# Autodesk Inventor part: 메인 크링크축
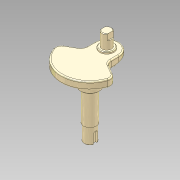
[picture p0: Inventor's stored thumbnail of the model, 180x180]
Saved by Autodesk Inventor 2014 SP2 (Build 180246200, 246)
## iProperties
Manager: KYOUNG IL JANG
Company: 한국ATC센터
Created: 2012-10
Part Number: 메인 크링크축
Document SubType Name: Modeling
Density: 1 g/cm^3
Checked By: KYOUNG IL JANG
Vendor: CBT Solutions
Designer: KYOUNG IL JANG
Material: 일반
Appearance: _시험_금속-티타늄(광택)
크링크폭: 19.000 mm
크랭크길이: 18.000 mm
크랭키위치: 65.000 mm
무게추: 90.000 mm
크랭크각도높이: 21.000 mm
크링크각도: -15.00 deg
Author: KYOUNG IL JANG
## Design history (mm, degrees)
sketch "스케치1"
  geometry: L1 (-19, 109.368)-(-19, 91.368); L2 (-19, 91.368)-(-44.545, 76.619); L3 (19, 109.368)-(19, 91.368); L4 (19, 91.368)-(44.545, 76.619); C1 r 32.5 at (0, 83) reference; C2 r 10 at (0, 83); C3 r 17.5 at (0, 83); A1 r 45 centre (0, 83) between (-44.545, 76.619) and (44.545, 76.619); A2 r 32.5 centre (0, 83) between (-19, 109.368) and (19, 109.368); A3 r 19 centre (0, 109.368) between (19, 109.368) and (-19, 109.368); 1 further point
  constraints: 8 end point, 6 point on circle, 5 centre point, 4 coincident, 2 equal length, 2 vertical alignment, 1 horizontal alignment, 1 parallel, 1 tangent, 1 vertical, 3 other
  dimensions: "d0" = 20 diameter of C2; "d1" = 35 diameter of C3; "d4" = 120 deg angle of L3 L4
  node "참조1"
extrude "돌출1" new body sketch "스케치1" distance "d7" = 12; taper "d8" = 0 deg
extrude "돌출2" join sketch "스케치1" distance "d9" = 5; taper "d10" = 0 deg
extrude "돌출3" join sketch "스케치1" distance "d11" = 100; taper "d12" = 0 deg
sketch "스케치2"
  geometry: C1 r 7.5 at (0, 109.368); C2 r 11 at (0, 109.368); A1 r 19 centre (0, 109.368) between (19, 109.368) and (-19, 109.368) reference; 1 further point
  constraints: 2 centre point, 2 coincident
  dimensions: "d13" = 15 diameter of C1; "d14" = 22 diameter of C2
extrude "돌출4" join sketch "스케치2" distance "d15" = 3; taper "d16" = 0 deg
extrude "돌출5" join sketch "스케치2" distance "d17" = 25; taper "d18" = 0 deg
node "작업 평면1"
sketch "스케치3"
  geometry: L1 (-5.75, 4.815)-(-5.75, -4.815); L2 (5.75, 4.815)-(5.75, -4.815); A1 r 7.5 centre (0, 0) between (-5.75, 4.815) and (-5.75, -4.815) reference; 1 further point
  constraints: 4 end point, 4 point on circle, 2 parallel, 1 vertical
  dimensions: "d20" = 11.5 distance between parallel lines of L2 L1
extrude "돌출6" cut sketch "스케치3" stored distance "d21" = 10; taper "d22" = 0 deg
sketch "스케치4"
  geometry: L1 (-19, 91.368)-(-19, 109.368) reference; L2 (19, 109.368)-(19, 91.368) reference; C1 r 17.5 at (0, 83) reference; 3 further points
  constraints: 2 point on line, 1 horizontal alignment, 1 other
node "작업 평면2"
  node "작업축1"
sketch "스케치5"
  geometry: L1 (0, 0)-(38, 0); L2 (38, 0)-(38, 50); L3 (38, 50)-(0, 50); L4 (0, 50)-(0, 0); L5 (38, 5.185)-(38, -12.202) reference; 2 further points
  constraints: 8 end point, 1 coincident, 1 collinear, 1 horizontal, 1 perpendicular
  dimensions: "d27" = 50 distance between parallel lines of L3 L1
extrude "돌출7" cut sketch "스케치5" stored distance "d28" = 10; taper "d29" = 0 deg
fillet "모깎기1" dims "d23" = 10, "d24" = 2
sketch "스케치6"
  geometry: C1 r 17.5 at (0, 0) reference; C2 r 15 at (0, 0); 1 further point
  constraints: 1 centre point, 1 coincident
  dimensions: "d30" = 30 diameter of C2
extrude "돌출8" join sketch "스케치6" distance "d31" = 21; taper "d32" = 0 deg
sketch "스케치7"
  geometry: C1 r 10 at (0, 0) reference; C2 r 9 at (0, 0); 1 further point
  constraints: 1 centre point, 1 coincident
  dimensions: "d33" = 1 radial gap between concentric circles of C1 C2
extrude "돌출9" cut sketch "스케치7" distance "d34" = 25; taper "d35" = 0 deg
node "작업 평면3"
sketch "스케치8"
  geometry: L1 (-9, 0)-(9, 0) reference; L2 (-3, 0)-(-3, 15); L3 (3, 15)-(3, 0); A1 r 3 centre (0, 15) between (3, 15) and (-3, 15); 2 further points
  constraints: 4 end point, 2 perpendicular, 2 point on circle, 2 point on line, 2 tangent, 1 centre point, 1 midpoint, 1 vertical alignment
  dimensions: "d36" = 6 distance between parallel lines of L3 L2; "d37" = 18 dimension on A1 L1
extrude "돌출10" cut sketch "스케치8" distance "d38" = 3.5; taper "d39" = 0 deg
chamfer "모따기1" distance "d40" = 1; stored, may be unused: second distance "d41" = 2, angle "d42" = 45 deg
node "솔리드1"
node "투영된 루프1"
other parameters: "d19" = 13
